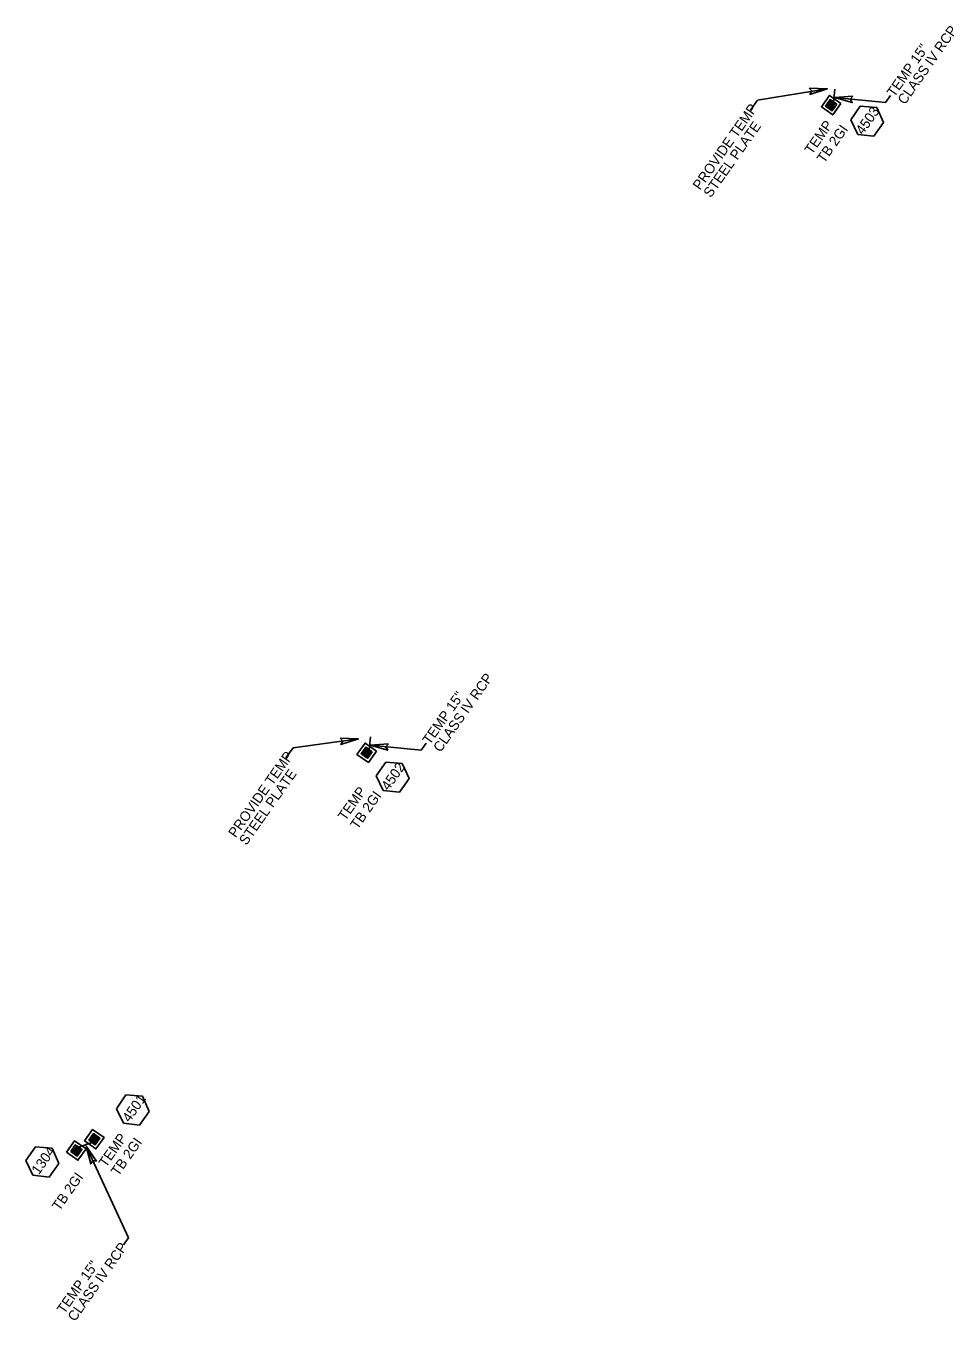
# Model space of a CAD drawing. Extents: x 2214978 to 2238755, y 984122 to 1016255.
# Drawn here: x 2216771 to 2217236, y 986569 to 987217 of the extents above; entities that cross this region are included whole.
import ezdxf

# ---------------------------------------------------------------- set-up
doc = ezdxf.new("R2010")
doc.units = 0
for name, color, linetype in [('Prop Drainage Structure Box Number Symbol CELL', 7, 'Continuous'), ('Prop Drainage Structure Drop Inlet Grate 2 Wide Slots and Sag Grates 840 22 TB CELL', 7, 'Continuous'), ('Prop Drainage Structure Drop Inlet Grate 2 Wide Slots and Sag Grates 840 22 TB Label', 7, 'Continuous'), ('Prop Drainage Structure Pipe Alternate 15in', 7, 'Continuous'), ('Prop Drainage Structure Pipe RCP 15in Class IV', 7, 'Continuous'), ('Prop Drainage Structure Plot Symbol 20 Scale', 7, 'Continuous'), ('Prop Drainage Structure Plot Symbol 50 Scale', 7, 'Continuous'), ('Prop Plan Preparation Drainage Notes Label', 7, 'Continuous')]:
    doc.layers.add(name, color=color, linetype=linetype)

msp = doc.modelspace()

# ---------------------------------------------------------------- linework, layer by layer
at = {"layer": 'Prop Drainage Structure Box Number Symbol CELL'}
for p, q in [((2217184.65, 987169.75), (2217189.48, 987176.61)), ((2217189.48, 987176.61), (2217197.78, 987175.99)), ((2217201.15, 987168.38), (2217197.78, 987175.99)), ((2217184.65, 987169.75), (2217188.16, 987162.47)), ((2217196.31, 987161.52), (2217201.15, 987168.38)), ((2217196.31, 987161.52), (2217188.16, 987162.47)), ((2216946.86, 986841.13), (2216951.7, 986847.99)), ((2216951.7, 986847.99), (2216959.99, 986847.37)), ((2216963.37, 986839.77), (2216959.99, 986847.37)), ((2216946.86, 986841.13), (2216950.38, 986833.86)), ((2216958.53, 986832.9), (2216963.37, 986839.77)), ((2216958.53, 986832.9), (2216950.38, 986833.86)), ((2216816.71, 986674.43), (2216821.54, 986681.29)), ((2216821.54, 986681.29), (2216829.84, 986680.67)), ((2216816.71, 986674.43), (2216820.23, 986667.15)), ((2216833.21, 986673.07), (2216829.84, 986680.67)), ((2216828.37, 986666.2), (2216833.21, 986673.07)), ((2216828.37, 986666.2), (2216820.23, 986667.15)), ((2216771.38, 986648.39), (2216776.22, 986655.26)), ((2216776.22, 986655.26), (2216784.52, 986654.63)), ((2216787.89, 986647.03), (2216784.52, 986654.63)), ((2216771.38, 986648.39), (2216774.9, 986641.12)), ((2216783.05, 986640.17), (2216787.89, 986647.03)), ((2216783.05, 986640.17), (2216774.9, 986641.12))]:
    msp.add_line(p, q, dxfattribs=at)
at = {"layer": 'Prop Drainage Structure Drop Inlet Grate 2 Wide Slots and Sag Grates 840 22 TB CELL'}
for p, q in [((2217173.7, 987175.51), (2217173.7, 987175.51)), ((2217173.9, 987177.82), (2217173.9, 987177.82)), ((2217174.85, 987177.15), (2217174.85, 987177.15)), ((2217175.8, 987176.47), (2217175.8, 987176.47)), ((2217176, 987178.78), (2217176, 987178.78)), ((2216941.01, 986851.09), (2216941.01, 986851.09)), ((2216941.21, 986853.4), (2216941.21, 986853.4)), ((2216942.16, 986852.73), (2216942.16, 986852.73)), ((2216943.12, 986852.06), (2216943.12, 986852.06)), ((2216943.31, 986854.36), (2216943.31, 986854.36)), ((2216797.79, 986655.14), (2216797.79, 986655.14)), ((2216804.52, 986657.48), (2216804.52, 986657.48)), ((2216804.72, 986659.79), (2216804.72, 986659.79)), ((2216805.67, 986659.12), (2216805.67, 986659.12)), ((2216806.62, 986658.45), (2216806.62, 986658.45)), ((2216806.82, 986660.75), (2216806.82, 986660.75)), ((2216795.49, 986651.87), (2216795.49, 986651.87)), ((2216795.69, 986654.18), (2216795.69, 986654.18)), ((2216796.64, 986653.5), (2216796.64, 986653.5)), ((2216797.59, 986652.83), (2216797.59, 986652.83))]:
    msp.add_line(p, q, dxfattribs=at)
for points in [[(2217176.95, 987178.11), (2217174.65, 987174.84), (2217172.74, 987176.18), (2217175.05, 987179.45), (2217176.95, 987178.11)], [(2217176.87, 987178.09), (2217174.64, 987174.93), (2217172.83, 987176.2), (2217175.06, 987179.37), (2217176.87, 987178.09), (2217176.87, 987178.09)], [(2217175.74, 987176.51), (2217174.63, 987174.94), (2217172.84, 987176.2), (2217173.95, 987177.77), (2217175.74, 987176.51)], [(2217173.75, 987176.69), (2217173.27, 987176), (2217173.05, 987176.16), (2217173.53, 987176.84), (2217173.75, 987176.69)], [(2217174.06, 987176.46), (2217173.58, 987175.78), (2217173.36, 987175.94), (2217173.84, 987176.62), (2217174.06, 987176.46)], [(2217174.28, 987177.44), (2217173.8, 987176.75), (2217173.57, 987176.91), (2217174.05, 987177.59), (2217174.28, 987177.44)], [(2217174.38, 987176.24), (2217173.9, 987175.56), (2217173.68, 987175.72), (2217174.16, 987176.4), (2217174.38, 987176.24)], [(2217174.59, 987177.21), (2217174.11, 987176.53), (2217173.89, 987176.69), (2217174.37, 987177.37), (2217174.59, 987177.21)], [(2217176.85, 987178.09), (2217175.75, 987176.52), (2217173.96, 987177.78), (2217175.07, 987179.35), (2217176.85, 987178.09)], [(2217174.69, 987176.02), (2217174.21, 987175.34), (2217173.99, 987175.49), (2217174.47, 987176.18), (2217174.69, 987176.02)], [(2217174.86, 987178.27), (2217174.38, 987177.59), (2217174.16, 987177.74), (2217174.64, 987178.43), (2217174.86, 987178.27)], [(2217174.91, 987176.99), (2217174.43, 987176.31), (2217174.2, 987176.47), (2217174.68, 987177.15), (2217174.91, 987176.99)], [(2217175.01, 987175.8), (2217174.53, 987175.12), (2217174.31, 987175.27), (2217174.79, 987175.95), (2217175.01, 987175.8)], [(2217175.18, 987178.05), (2217174.7, 987177.37), (2217174.48, 987177.52), (2217174.96, 987178.2), (2217175.18, 987178.05)], [(2217175.22, 987176.77), (2217174.74, 987176.09), (2217174.52, 987176.24), (2217175, 987176.92), (2217175.22, 987176.77)], [(2217175.39, 987179.02), (2217174.91, 987178.34), (2217174.69, 987178.49), (2217175.17, 987179.17), (2217175.39, 987179.02)], [(2217175.49, 987177.83), (2217175.01, 987177.14), (2217174.79, 987177.3), (2217175.27, 987177.98), (2217175.49, 987177.83)], [(2217175.54, 987176.55), (2217175.06, 987175.87), (2217174.83, 987176.02), (2217175.31, 987176.7), (2217175.54, 987176.55)], [(2217175.71, 987178.8), (2217175.23, 987178.12), (2217175.01, 987178.27), (2217175.49, 987178.95), (2217175.71, 987178.8)], [(2217175.81, 987177.6), (2217175.33, 987176.92), (2217175.11, 987177.08), (2217175.59, 987177.76), (2217175.81, 987177.6)], [(2217176.02, 987178.57), (2217175.54, 987177.89), (2217175.32, 987178.05), (2217175.8, 987178.73), (2217176.02, 987178.57)], [(2217176.12, 987177.38), (2217175.64, 987176.7), (2217175.42, 987176.86), (2217175.9, 987177.54), (2217176.12, 987177.38)], [(2217176.34, 987178.35), (2217175.86, 987177.67), (2217175.64, 987177.83), (2217176.12, 987178.51), (2217176.34, 987178.35)], [(2217176.65, 987178.13), (2217176.17, 987177.45), (2217175.95, 987177.61), (2217176.43, 987178.29), (2217176.65, 987178.13)], [(2216944.27, 986853.69), (2216941.96, 986850.42), (2216940.06, 986851.77), (2216942.36, 986855.04), (2216944.27, 986853.69)], [(2216944.18, 986853.68), (2216941.95, 986850.51), (2216940.14, 986851.78), (2216942.38, 986854.95), (2216944.18, 986853.68), (2216944.18, 986853.68)], [(2216943.05, 986852.09), (2216941.95, 986850.52), (2216940.16, 986851.78), (2216941.26, 986853.35), (2216943.05, 986852.09)], [(2216941.06, 986852.27), (2216940.58, 986851.59), (2216940.36, 986851.74), (2216940.84, 986852.43), (2216941.06, 986852.27)], [(2216941.38, 986852.05), (2216940.9, 986851.37), (2216940.67, 986851.52), (2216941.15, 986852.2), (2216941.38, 986852.05)], [(2216941.59, 986853.02), (2216941.11, 986852.34), (2216940.89, 986852.49), (2216941.37, 986853.17), (2216941.59, 986853.02)], [(2216941.69, 986851.83), (2216941.21, 986851.14), (2216940.99, 986851.3), (2216941.47, 986851.98), (2216941.69, 986851.83)], [(2216941.9, 986852.8), (2216941.42, 986852.12), (2216941.2, 986852.27), (2216941.68, 986852.95), (2216941.9, 986852.8)], [(2216944.17, 986853.67), (2216943.06, 986852.11), (2216941.27, 986853.37), (2216942.38, 986854.93), (2216944.17, 986853.67)], [(2216942.01, 986851.6), (2216941.53, 986850.92), (2216941.3, 986851.08), (2216941.78, 986851.76), (2216942.01, 986851.6)], [(2216942.18, 986853.85), (2216941.7, 986853.17), (2216941.48, 986853.33), (2216941.96, 986854.01), (2216942.18, 986853.85)], [(2216942.22, 986852.57), (2216941.74, 986851.89), (2216941.52, 986852.05), (2216942, 986852.73), (2216942.22, 986852.57)], [(2216942.32, 986851.38), (2216941.84, 986850.7), (2216941.62, 986850.86), (2216942.1, 986851.54), (2216942.32, 986851.38)], [(2216942.49, 986853.63), (2216942.01, 986852.95), (2216941.79, 986853.11), (2216942.27, 986853.79), (2216942.49, 986853.63)], [(2216942.53, 986852.35), (2216942.05, 986851.67), (2216941.83, 986851.83), (2216942.31, 986852.51), (2216942.53, 986852.35)], [(2216942.71, 986854.6), (2216942.23, 986853.92), (2216942, 986854.08), (2216942.48, 986854.76), (2216942.71, 986854.6)], [(2216942.81, 986853.41), (2216942.33, 986852.73), (2216942.11, 986852.88), (2216942.59, 986853.57), (2216942.81, 986853.41)], [(2216942.85, 986852.13), (2216942.37, 986851.45), (2216942.15, 986851.61), (2216942.63, 986852.29), (2216942.85, 986852.13)], [(2216943.02, 986854.38), (2216942.54, 986853.7), (2216942.32, 986853.86), (2216942.8, 986854.54), (2216943.02, 986854.38)], [(2216943.12, 986853.19), (2216942.64, 986852.51), (2216942.42, 986852.66), (2216942.9, 986853.34), (2216943.12, 986853.19)], [(2216943.34, 986854.16), (2216942.86, 986853.48), (2216942.63, 986853.63), (2216943.11, 986854.31), (2216943.34, 986854.16)], [(2216943.44, 986852.97), (2216942.96, 986852.28), (2216942.74, 986852.44), (2216943.22, 986853.12), (2216943.44, 986852.97)], [(2216943.65, 986853.94), (2216943.17, 986853.26), (2216942.95, 986853.41), (2216943.43, 986854.09), (2216943.65, 986853.94)], [(2216943.97, 986853.71), (2216943.49, 986853.03), (2216943.26, 986853.19), (2216943.74, 986853.87), (2216943.97, 986853.71)], [(2216803.56, 986658.16), (2216805.87, 986661.43), (2216807.78, 986660.08), (2216805.47, 986656.81), (2216803.56, 986658.16)], [(2216794.53, 986652.54), (2216796.84, 986655.81), (2216798.75, 986654.47), (2216796.44, 986651.2), (2216794.53, 986652.54)], [(2216794.62, 986652.56), (2216796.85, 986655.72), (2216798.66, 986654.45), (2216796.43, 986651.28), (2216794.62, 986652.56), (2216794.62, 986652.56)], [(2216795.75, 986654.14), (2216796.86, 986655.71), (2216798.64, 986654.45), (2216797.54, 986652.88), (2216795.75, 986654.14)], [(2216796.48, 986654.85), (2216796.96, 986655.53), (2216797.18, 986655.38), (2216796.7, 986654.7), (2216796.48, 986654.85)], [(2216796.8, 986654.63), (2216797.28, 986655.31), (2216797.5, 986655.16), (2216797.02, 986654.47), (2216796.8, 986654.63)], [(2216797.11, 986654.41), (2216797.59, 986655.09), (2216797.81, 986654.93), (2216797.33, 986654.25), (2216797.11, 986654.41)], [(2216803.65, 986658.17), (2216805.88, 986661.34), (2216807.69, 986660.07), (2216805.46, 986656.9), (2216803.65, 986658.17), (2216803.65, 986658.17)], [(2216803.67, 986658.17), (2216804.77, 986659.74), (2216806.56, 986658.48), (2216805.45, 986656.91), (2216803.67, 986658.17)], [(2216803.87, 986658.13), (2216804.35, 986658.81), (2216804.57, 986658.66), (2216804.09, 986657.98), (2216803.87, 986658.13)], [(2216804.18, 986657.91), (2216804.66, 986658.59), (2216804.88, 986658.44), (2216804.4, 986657.76), (2216804.18, 986657.91)], [(2216804.4, 986658.88), (2216804.88, 986659.56), (2216805.1, 986659.41), (2216804.62, 986658.73), (2216804.4, 986658.88)], [(2216804.5, 986657.69), (2216804.98, 986658.37), (2216805.2, 986658.21), (2216804.72, 986657.53), (2216804.5, 986657.69)], [(2216804.71, 986658.66), (2216805.19, 986659.34), (2216805.41, 986659.19), (2216804.93, 986658.5), (2216804.71, 986658.66)], [(2216804.78, 986659.76), (2216805.89, 986661.32), (2216807.67, 986660.06), (2216806.57, 986658.5), (2216804.78, 986659.76)], [(2216804.81, 986657.47), (2216805.29, 986658.15), (2216805.51, 986657.99), (2216805.03, 986657.31), (2216804.81, 986657.47)], [(2216804.98, 986659.72), (2216805.46, 986660.4), (2216805.69, 986660.24), (2216805.21, 986659.56), (2216804.98, 986659.72)], [(2216805.03, 986658.44), (2216805.51, 986659.12), (2216805.73, 986658.96), (2216805.25, 986658.28), (2216805.03, 986658.44)], [(2216805.13, 986657.25), (2216805.61, 986657.93), (2216805.83, 986657.77), (2216805.35, 986657.09), (2216805.13, 986657.25)], [(2216805.3, 986659.5), (2216805.78, 986660.18), (2216806, 986660.02), (2216805.52, 986659.34), (2216805.3, 986659.5)], [(2216805.34, 986658.22), (2216805.82, 986658.9), (2216806.04, 986658.74), (2216805.56, 986658.06), (2216805.34, 986658.22)], [(2216805.51, 986660.47), (2216805.99, 986661.15), (2216806.21, 986660.99), (2216805.73, 986660.31), (2216805.51, 986660.47)], [(2216805.61, 986659.27), (2216806.09, 986659.95), (2216806.32, 986659.8), (2216805.84, 986659.12), (2216805.61, 986659.27)], [(2216805.66, 986657.99), (2216806.14, 986658.68), (2216806.36, 986658.52), (2216805.88, 986657.84), (2216805.66, 986657.99)], [(2216805.83, 986660.24), (2216806.31, 986660.93), (2216806.53, 986660.77), (2216806.05, 986660.09), (2216805.83, 986660.24)], [(2216805.93, 986659.05), (2216806.41, 986659.73), (2216806.63, 986659.58), (2216806.15, 986658.9), (2216805.93, 986659.05)], [(2216806.14, 986660.02), (2216806.62, 986660.7), (2216806.84, 986660.55), (2216806.36, 986659.87), (2216806.14, 986660.02)], [(2216806.24, 986658.83), (2216806.72, 986659.51), (2216806.95, 986659.35), (2216806.47, 986658.67), (2216806.24, 986658.83)], [(2216806.46, 986659.8), (2216806.94, 986660.48), (2216807.16, 986660.33), (2216806.68, 986659.64), (2216806.46, 986659.8)], [(2216806.77, 986659.58), (2216807.25, 986660.26), (2216807.47, 986660.1), (2216806.99, 986659.42), (2216806.77, 986659.58)], [(2216794.64, 986652.56), (2216795.74, 986654.13), (2216797.53, 986652.87), (2216796.42, 986651.3), (2216794.64, 986652.56)], [(2216794.84, 986652.52), (2216795.32, 986653.2), (2216795.54, 986653.04), (2216795.06, 986652.36), (2216794.84, 986652.52)], [(2216795.15, 986652.3), (2216795.63, 986652.98), (2216795.85, 986652.82), (2216795.37, 986652.14), (2216795.15, 986652.3)], [(2216795.36, 986653.27), (2216795.85, 986653.95), (2216796.07, 986653.79), (2216795.59, 986653.11), (2216795.36, 986653.27)], [(2216795.47, 986652.08), (2216795.95, 986652.76), (2216796.17, 986652.6), (2216795.69, 986651.92), (2216795.47, 986652.08)], [(2216795.68, 986653.05), (2216796.16, 986653.73), (2216796.38, 986653.57), (2216795.9, 986652.89), (2216795.68, 986653.05)], [(2216795.78, 986651.85), (2216796.26, 986652.53), (2216796.48, 986652.38), (2216796, 986651.7), (2216795.78, 986651.85)], [(2216795.95, 986654.1), (2216796.43, 986654.78), (2216796.65, 986654.63), (2216796.17, 986653.95), (2216795.95, 986654.1)], [(2216795.99, 986652.82), (2216796.48, 986653.51), (2216796.7, 986653.35), (2216796.22, 986652.67), (2216795.99, 986652.82)], [(2216796.1, 986651.63), (2216796.58, 986652.31), (2216796.8, 986652.16), (2216796.32, 986651.48), (2216796.1, 986651.63)], [(2216796.27, 986653.88), (2216796.75, 986654.56), (2216796.97, 986654.41), (2216796.49, 986653.72), (2216796.27, 986653.88)], [(2216796.31, 986652.6), (2216796.79, 986653.28), (2216797.01, 986653.13), (2216796.53, 986652.45), (2216796.31, 986652.6)], [(2216796.58, 986653.66), (2216797.06, 986654.34), (2216797.28, 986654.18), (2216796.8, 986653.5), (2216796.58, 986653.66)], [(2216796.63, 986652.38), (2216797.11, 986653.06), (2216797.33, 986652.91), (2216796.85, 986652.22), (2216796.63, 986652.38)], [(2216796.9, 986653.44), (2216797.38, 986654.12), (2216797.6, 986653.96), (2216797.12, 986653.28), (2216796.9, 986653.44)], [(2216797.21, 986653.21), (2216797.69, 986653.9), (2216797.91, 986653.74), (2216797.43, 986653.06), (2216797.21, 986653.21)], [(2216797.43, 986654.19), (2216797.91, 986654.87), (2216798.13, 986654.71), (2216797.65, 986654.03), (2216797.43, 986654.19)], [(2216797.74, 986653.96), (2216798.22, 986654.64), (2216798.44, 986654.49), (2216797.96, 986653.81), (2216797.74, 986653.96)]]:
    msp.add_lwpolyline(points, dxfattribs=at)
at = {"layer": 'Prop Drainage Structure Pipe Alternate 15in'}
for p, q in [((2217176, 987178.78), (2217176.69, 987185.13)), ((2216804.52, 986657.48), (2216797.79, 986655.14))]:
    msp.add_line(p, q, dxfattribs=at)
at = {"layer": 'Prop Drainage Structure Pipe RCP 15in Class IV'}
msp.add_line((2216944, 986860.71), (2216943.31, 986854.36), dxfattribs=at)
at = {"layer": 'Prop Drainage Structure Plot Symbol 20 Scale'}
for points in [[(2217177.64, 987177.63), (2217175.33, 987174.36), (2217172.06, 987176.66), (2217174.37, 987179.93)], [(2216944.95, 986853.21), (2216942.64, 986849.94), (2216939.38, 986852.25), (2216941.68, 986855.52)], [(2216802.88, 986658.64), (2216805.19, 986661.91), (2216808.46, 986659.6), (2216806.15, 986656.33)], [(2216793.85, 986653.02), (2216796.16, 986656.29), (2216799.43, 986653.99), (2216797.12, 986650.72)]]:
    msp.add_lwpolyline(points, close=True, dxfattribs=at)
at = {"layer": 'Prop Drainage Structure Plot Symbol 50 Scale'}
for points in [[(2217179.73, 987177.99), (2217175.69, 987172.27), (2217169.97, 987176.3), (2217174.01, 987182.02)], [(2216947.04, 986853.57), (2216943.01, 986847.85), (2216937.28, 986851.89), (2216941.32, 986857.61)], [(2216800.79, 986658.27), (2216804.83, 986664), (2216810.55, 986659.96), (2216806.51, 986654.24)], [(2216791.76, 986652.66), (2216795.8, 986658.38), (2216801.52, 986654.35), (2216797.48, 986648.63)]]:
    msp.add_lwpolyline(points, close=True, dxfattribs=at)
at = {"layer": 'Prop Plan Preparation Drainage Notes Label'}
for p, q in [((2217137.93, 987179.66), (2217172.95, 987185.32)), ((2217202.08, 987178.4), (2217176.58, 987180.92)), ((2217204.56, 987181.91), (2217202.08, 987178.4)), ((2217137.93, 987179.66), (2217134.38, 987174.62)), ((2216905.25, 986855.25), (2216938.02, 986859.63)), ((2216969.4, 986853.98), (2216943.89, 986856.51)), ((2216971.87, 986857.49), (2216969.4, 986853.98)), ((2216905.25, 986855.25), (2216901.69, 986850.2)), ((2216822.79, 986609.66), (2216801.54, 986655.67)), ((2216822.79, 986609.66), (2216820.32, 986606.15))]:
    msp.add_line(p, q, dxfattribs=at)
for points in [[(2217163.82, 987185.66), (2217172.95, 987185.32), (2217164.19, 987182.53), (2217165.12, 987184.27)], [(2217185.69, 987181.58), (2217176.58, 987180.92), (2217185.43, 987178.44), (2217184.44, 987180.15)], [(2216928.89, 986859.98), (2216938.02, 986859.63), (2216929.26, 986856.85), (2216930.19, 986858.59)], [(2216953, 986857.16), (2216943.89, 986856.51), (2216952.74, 986854.02), (2216951.75, 986855.73)], [(2216806.72, 986648.15), (2216801.54, 986655.67), (2216803.88, 986646.79), (2216804.85, 986648.5)]]:
    msp.add_lwpolyline(points, close=True, dxfattribs=at)

# ---------------------------------------------------------------- texts
at = {"layer": 'Prop Drainage Structure Box Number Symbol CELL'}
for s, p in [('4503', (2217190.81, 987161.92)), ('4502', (2216953.11, 986833.42)), ('4501', (2216823.33, 986667.24)), ('1304', (2216777.87, 986641.02))]:
    msp.add_text(s, height=5, rotation=54.81679, dxfattribs=at).set_placement(p)
at = {"layer": 'Prop Drainage Structure Drop Inlet Grate 2 Wide Slots and Sag Grates 840 22 TB Label'}
for s, p in [('TEMP', (2217165.27, 987152.05)), ('TB 2GI', (2217171.4, 987147.73)), ('TEMP', (2216931.48, 986818.26)), ('TB 2GI', (2216937.61, 986813.94)), ('TEMP', (2216811.55, 986644.63)), ('TB 2GI', (2216817.68, 986640.3)), ('TB 2GI', (2216788.2, 986622.87))]:
    msp.add_text(s, height=5, rotation=54.81679, dxfattribs=at).set_placement(p)
at = {"layer": 'Prop Plan Preparation Drainage Notes Label'}
for s, rotation, p in [('CLASS IV RCP', 54.87318, (2217211.86, 987177.03)), ('TEMP 15"', 54.87318, (2217206.5, 987180.8)), ('PROVIDE TEMP', 54.83068, (2217109.2, 987134.24)), ('STEEL PLATE', 54.83068, (2217114.56, 987130.47)), ('CLASS IV RCP', 54.87318, (2216979.18, 986852.61)), ('TEMP 15"', 54.87318, (2216973.82, 986856.38)), ('PROVIDE TEMP', 54.83068, (2216876.51, 986809.83)), ('STEEL PLATE', 54.83068, (2216881.87, 986806.05)), ('CLASS IV RCP', 54.87318, (2216796.01, 986567.47)), ('TEMP 15"', 54.87318, (2216790.65, 986571.25))]:
    msp.add_text(s, height=5, rotation=rotation, dxfattribs=at).set_placement(p)

doc.saveas('drawing.dxf')
